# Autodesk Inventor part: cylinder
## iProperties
Shininess: 64.0
Length Units: 11269
Angle Units: 11279
Time Units: 11290
Mass Units: 11283
Length Display Precision: 3
Angle Display Precision: 2
Compacted: True
Part Number: cylinder
Document SubType Name: Modeling
Created: 2003-01
Designer: Owner
Density: 0.0
Volumn: 0.0
Area: 0.0
PropertySet Name: Model Information
Control State: 0
Master: False
Checked Out: False
Author: Owner
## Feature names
1. Extrusion1
